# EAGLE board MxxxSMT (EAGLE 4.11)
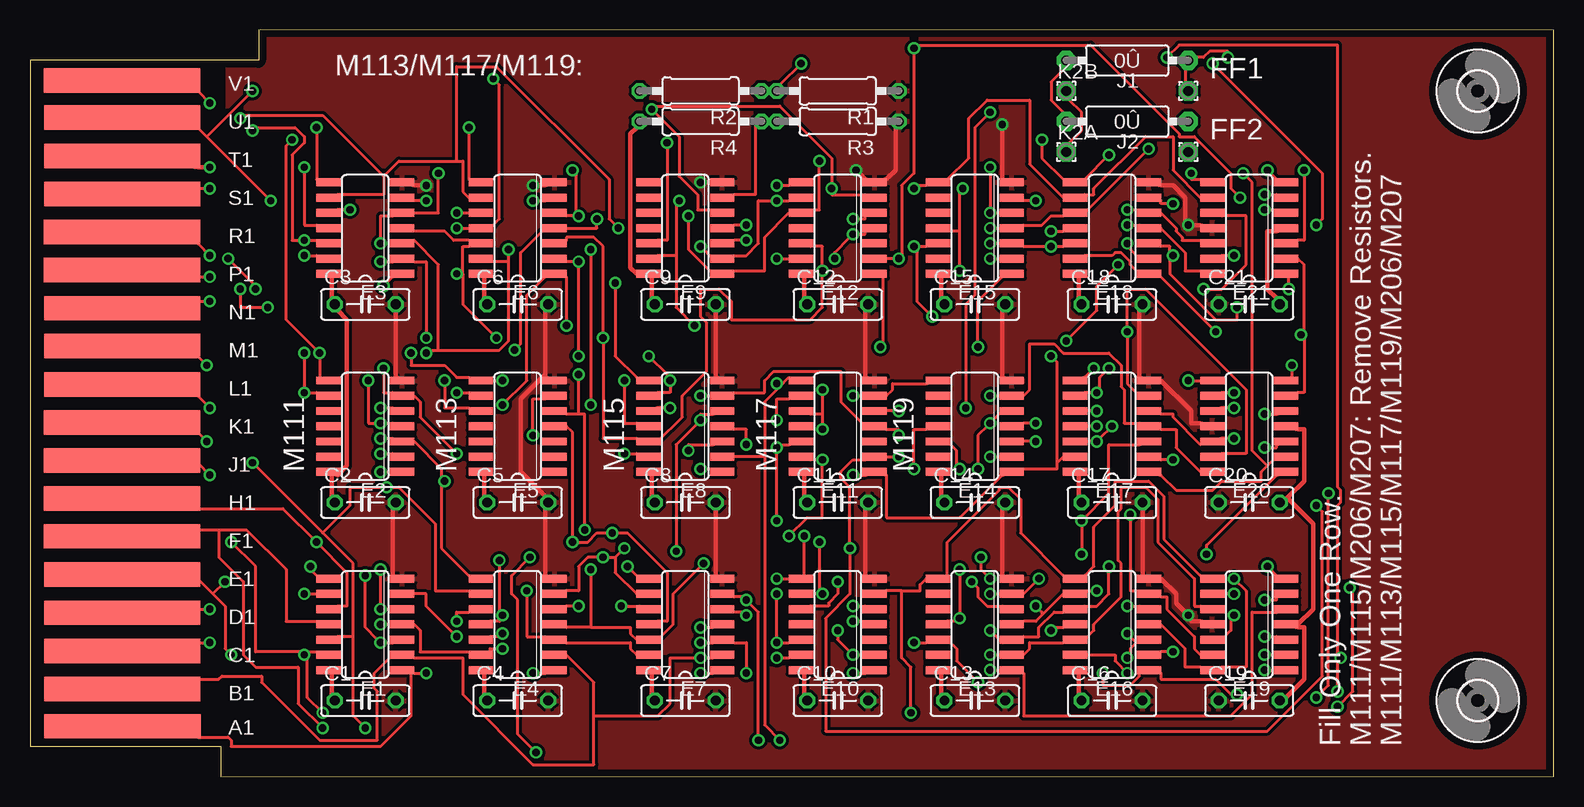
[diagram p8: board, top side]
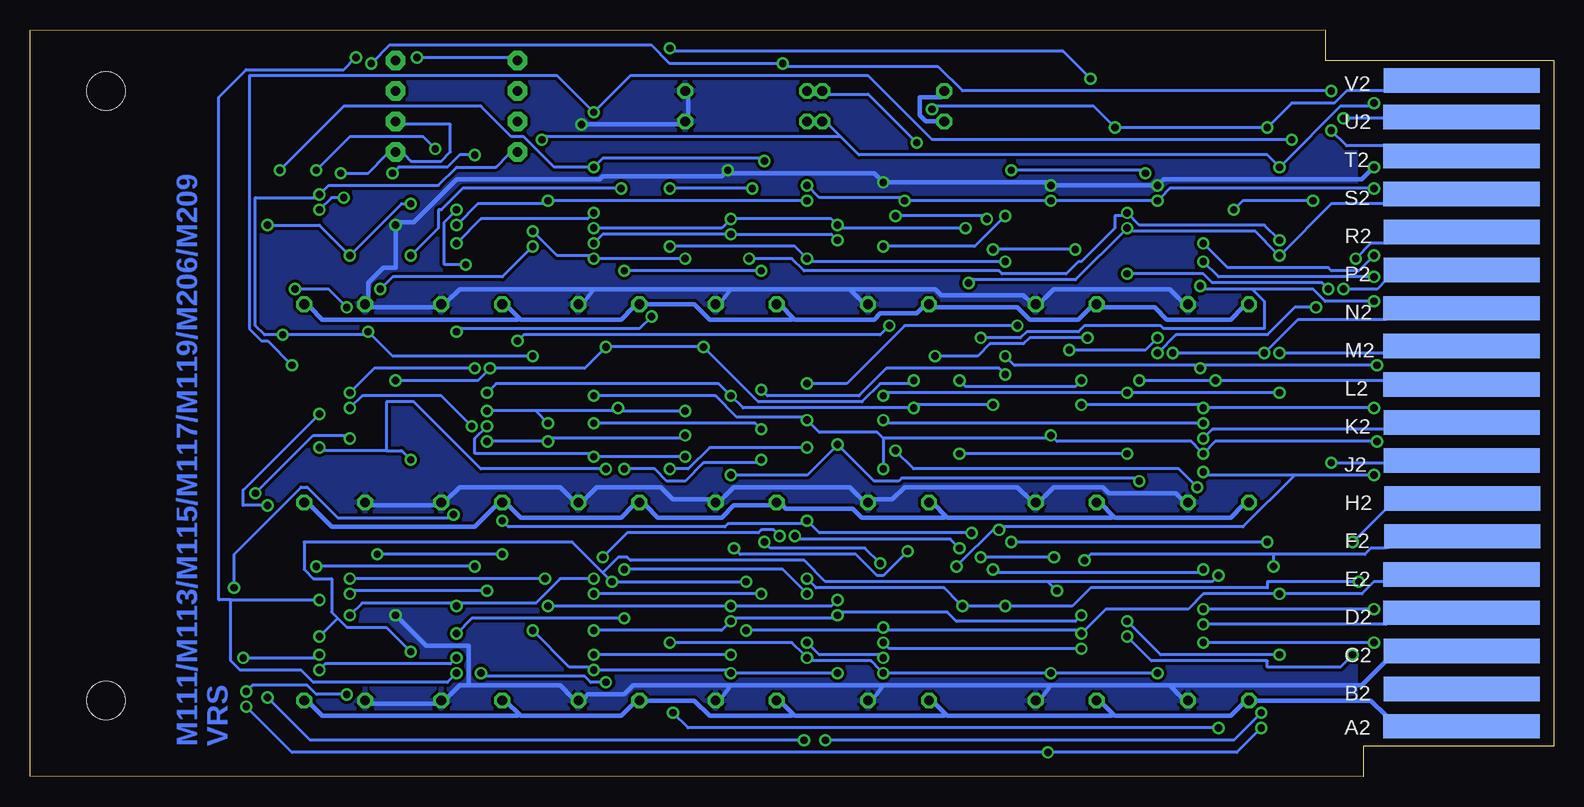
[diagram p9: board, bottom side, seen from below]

Size 126.99 x 62.23 mm. Coordinates in mm from the lower left corner, seen from the top.
Outline: 15.88,0 126.99,0.04 126.99,62.19 19.18,62.23
Copper layers (1*16): Top 0.035mm / dielectric 1.5mm / Bottom 0.035mm
Design rules "olimex10mil": minimum track width 10mil, minimum drill 24mil, track to track 10mil, track to pad 10mil, pad to pad 10mil, via to via 10mil, smd to smd 10mil, copper to edge 25mil, drill to drill 10mil, minimum pad ring 10mil, minimum via ring 8mil, stop-mask expansion 0mil, vias tented up to drill 0mil, thermal gap 10mil
Net classes: 1 Power: width 0.381 mm

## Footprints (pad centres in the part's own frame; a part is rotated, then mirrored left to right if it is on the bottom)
C050-025X075 = drill 0.813 octagon: 1 -2.54,0; 2 2.54,0
SO14 = smd 0.66 x 2.032: 1 -3.81,-3.073; 2 -2.54,-3.073; 3 -1.27,-3.073; 4 0,-3.073; 5 1.27,-3.073; 6 2.54,-3.073; 7 3.81,-3.073; 8 3.81,3.073; 9 2.54,3.073; 10 1.27,3.073; 11 0,3.073; 12 -1.27,3.073; 13 -2.54,3.073; 14 -3.81,3.073
1,6/0,8 = drill 0.813 pad 1.6 octagon: 1 0,0
0R/10 = drill 0.813 pad 1.6 octagon: 1 -5.08,0; 2 5.08,0
0207/10 = drill 0.813 octagon: 1 -5.08,0; 2 5.08,0
EDGE-CON2 = smd 13.017 x 2.032: A1 7.709,4.207; B1 7.684,7.312; C1 7.684,10.474; D1 7.684,13.665; E1 7.693,16.84; F1 7.668,20.041; H1 7.668,23.19; J1 7.668,26.34; K1 7.668,29.515; L1 7.693,32.69; M1 7.693,35.89; N1 7.693,39.04; P1 7.668,42.24; R1 7.668,45.39; S1 7.693,48.565; T1 7.693,51.74; U1 7.693,54.94; V1 7.668,58.026 | smd 13.017 x 2.032 bottom: A2 7.69,4.207; B2 7.668,7.328; C2 7.668,10.49; D2 7.693,13.665; E2 7.693,16.84; F2 7.642,20.041; H2 7.642,23.19; J2 7.668,26.34; K2 7.668,29.515; L2 7.693,32.69; M2 7.693,35.89; N2 7.693,39.04; P2 7.668,42.24; R2 7.668,45.39; S2 7.693,48.565; T2 7.693,51.74; U2 7.693,54.966; V2 7.668,58.026
3,2 = hole 3.2: 0,0

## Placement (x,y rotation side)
C1  0.1uf  [C050-025X075]  27.94,6.35 0 top
C2  0.1uf  [C050-025X075]  27.94,22.86 0 top
C3  0.1uf  [C050-025X075]  27.94,39.37 0 top
C4  0.1uf  [C050-025X075]  40.64,6.35 0 top
C5  0.1uf  [C050-025X075]  40.64,22.86 0 top
C6  0.1uf  [C050-025X075]  40.64,39.37 0 top
C7  0.1uf  [C050-025X075]  54.61,6.35 0 top
C8  0.1uf  [C050-025X075]  54.61,22.86 0 top
C9  0.1uf  [C050-025X075]  54.61,39.37 0 top
C10  0.1uf  [C050-025X075]  67.31,6.35 0 top
C11  0.1uf  [C050-025X075]  67.31,22.86 0 top
C12  0.1uf  [C050-025X075]  67.31,39.37 0 top
C13  0.1uf  [C050-025X075]  78.74,6.35 0 top
C14  0.1uf  [C050-025X075]  78.74,22.86 0 top
C15  0.1uf  [C050-025X075]  78.74,39.37 0 top
C16  0.1uf  [C050-025X075]  90.17,6.35 0 top
C17  0.1uf  [C050-025X075]  90.17,22.86 0 top
C18  0.1uf  [C050-025X075]  90.17,39.37 0 top
C19  0.1uf  [C050-025X075]  101.6,6.35 180 top
C20  0.1uf  [C050-025X075]  101.6,22.86 180 top
C21  0.1uf  [C050-025X075]  101.6,39.37 180 top
E1  7404D  [SO14]  27.94,12.7 90 top
E2  7404D  [SO14]  27.94,29.21 90 top
E3  7404D  [SO14]  27.94,45.72 90 top
E4  7400D  [SO14]  40.64,12.7 90 top
E5  7400D  [SO14]  40.64,29.21 90 top
E6  7400D  [SO14]  40.64,45.72 90 top
E7  7410D  [SO14]  54.61,12.7 90 top
E8  7410D  [SO14]  54.61,29.21 90 top
E9  7410D  [SO14]  54.61,45.72 90 top
E10  7420D  [SO14]  67.31,12.7 90 top
E11  7420D  [SO14]  67.31,29.21 90 top
E12  7420D  [SO14]  67.31,45.72 90 top
E13  7430D  [SO14]  78.74,12.7 90 top
E14  7430D  [SO14]  78.74,29.21 90 top
E15  7430D  [SO14]  78.74,45.72 90 top
E16  7474D  [SO14]  90.17,12.7 90 top
E17  7474D  [SO14]  90.17,29.21 90 top
E18  7474D  [SO14]  90.17,45.72 90 top
E19  7473D  [SO14]  101.6,12.7 90 top
E20  7473D  [SO14]  101.6,29.21 90 top
E21  7473D  [SO14]  101.6,45.72 90 top
FF1  [1,6/0,8]  96.52,57.15 0 top
FF2  [1,6/0,8]  96.52,52.07 0 top
J1  [0R/10]  91.44,59.69 0 top
J2  [0R/10]  91.44,54.61 0 top
K2A  [1,6/0,8]  86.36,52.07 0 top
K2B  [1,6/0,8]  86.36,57.15 0 top
R1  750  [0207/10]  67.31,57.15 180 top
R2  330  [0207/10]  55.88,57.15 180 top
R3  750  [0207/10]  67.31,54.61 180 top
R4  330  [0207/10]  55.88,54.61 180 top
U$1  [EDGE-CON2]  0,0 0 top
U$2  [3,2]  120.65,6.35 0 top
U$3  [3,2]  120.65,57.15 0 top

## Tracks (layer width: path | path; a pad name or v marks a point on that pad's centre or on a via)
A1  (via drill 0.61)
  Top 0.254: J2.1 86.11,55.37 85.09,56.39 85.09,57.91 86.11,58.93 J1.1 | U$1.A1 13.97,3.3 16.51,3.3 16.76,3.05 16.76,2.54 29.21,2.54 31.75,5.08 31.75,8.64 E1.1 32,8.64 v33.02,8.64 | v41.91,8.64 42.93,8.64 E4.1 | v55.88,8.64 56.9,8.64 E7.1 | v62.23,9.91 63.25,9.91 E10.13 | v73.66,11.18 74.68,11.18 E13.12 76.45,11.43 77.22,10.67 77.22,9.65 v78.99,7.87 | v89.41,8.64 89.41,7.62 91.69,7.62 92.46,8.38 92.46,8.64 E16.1 94.23,8.64 94.23,8.13 98.81,8.13 100.08,6.86 v100.58,6.86 | v102.87,10.16 103.89,10.16 E19.2 | v108.97,7.11 108.97,9.65 v109.22,9.91 108.97,10.16 108.97,22.61 109.22,22.86 109.22,23.88 108.97,24.13 108.97,60.96 95.76,60.96 v94.74,59.94
  Bottom 0.254: v33.02,8.64 v41.91,8.64 42.16,8.64 v55.88,8.64 56.13,8.89 56.9,9.65 61.98,9.65 v62.23,9.91 62.48,10.16 63.5,11.18 v73.66,11.18 | v89.41,8.64 89.15,8.38 80.77,8.38 80.26,7.87 v78.99,7.87 | v102.87,10.16 103.12,9.91 v109.22,9.91 | v108.97,7.11 108.46,7.62 103.89,7.62 103.12,6.86 v100.58,6.86 | v94.74,59.94 87.12,59.94 J1.1
B1  (via drill 0.61)
  Top 0.254: v102.87,8.89 103.89,8.89 E19.1 | v91.44,9.91 91.69,10.16 91.69,10.67 92.2,11.18 | 92.2,11.18 92.46,11.43 E16.3 | v91.44,11.94 92.2,11.18 | E13.11 76.45,12.95 77.47,12.95 v77.47,13.21 77.47,13.46 v77.47,17.27 | 46.99,5.08 46.99,7.87 44.7,10.16 E4.2 | 46.99,5.08 46.99,1.02 41.91,1.02 36.07,6.86 36.07,9.91 32,9.91 E1.2 30.23,10.16 28.7,8.64 28.7,7.37 28.96,7.11 28.96,3.05 24.13,3.05 19.3,7.87 19.3,8.38 16,8.38 15.75,8.13 13.97,8.13 U$1.B1 | 46.99,5.08 52.32,5.08 53.34,6.1 53.34,9.91 v55.88,9.91 56.9,9.91 E7.2 | E10.12 63.25,11.18 v62.23,11.18 62.23,11.43 v62.23,15.24
  Bottom 0.254: v102.87,8.89 102.36,9.4 91.95,9.4 v91.44,9.91 | v77.47,13.21 90.17,13.21 v91.44,11.94 | v62.23,11.18 61.21,10.16 56.13,10.16 v55.88,9.91 | v77.47,17.27 64.26,17.27 v62.23,15.24
C1  (via drill 0.61)
  Top 0.254: v14.99,11.18 13.97,11.18 U$1.C1 | E1.3 30.23,11.18 v29.21,11.18 28.96,11.43 27.94,12.45 v27.94,16.76 | E7.13 50.55,10.16 50.04,10.67 50.04,11.18 44.7,11.18 E4.3 42.93,11.68 41.4,11.68 v41.4,15.49 | v67.31,16.26 67.31,15.24 66.55,14.48 66.55,14.22 65.02,14.22 E10.10 | v78.49,16.26 78.99,15.75 78.99,14.99 79.76,14.22 81.03,14.22 E13.5 | v95.25,10.41 94.23,10.41 E16.2 | v102.87,11.68 103.89,11.68 E19.3
  Bottom 0.254: v14.99,11.18 v29.21,11.18 | v67.31,16.26 v78.49,16.26 78.74,16.51 79.25,17.02 | v95.25,10.41 97.28,12.45 100.58,12.45 101.35,13.21 | 101.35,13.21 101.85,13.72 101.85,16.51 103.38,16.51 104.14,17.27 104.14,19.56 81.79,19.56 79.25,17.02 | 101.35,13.21 v102.87,11.68 | 42.16,16.26 v41.4,15.49 | 42.16,16.26 60.71,16.26 62.48,18.03 76.96,18.03 77.22,18.29 77.98,18.29 79.25,17.02 | v27.94,16.76 28.45,16.26 42.16,16.26
D1  (via drill 0.61)
  Top 0.254: E16.4 94.23,12.7 96.27,10.67 96.27,9.14 97.54,9.14 E19.14 99.31,9.14 101.35,9.14 101.35,15.49 v100.33,16.51 | v80.01,15.24 81.03,15.24 E13.6 82.8,15.24 v84.07,16.51 | E10.9 65.02,15.24 v66.04,15.24 65.79,15.49 v65.79,19.56 | 46.74,12.45 50.04,12.45 50.04,11.94 50.55,11.43 E7.12 52.32,11.43 53.59,12.7 53.59,15.24 v56.13,17.78 | 46.74,12.45 44.7,12.45 E4.4 | v14.99,13.97 13.97,13.97 U$1.D1 | E1.5 30.23,13.97 v29.21,13.97 29.21,14.22 v29.21,17.27 | v46.74,17.27 46.74,12.45
  Bottom 0.254: v66.04,15.24 v80.01,15.24 | v84.07,16.51 v100.33,16.51 | v14.99,13.97 v29.21,13.97 | v46.74,17.27 46.48,17.02 29.46,17.02 v29.21,17.27 | v65.79,19.56 65.28,19.05 57.4,19.05 v56.13,17.78
D2  (via drill 0.61)
  Top 0.254: v59.69,8.64 59.69,11.18 58.67,11.18 E7.3 56.9,11.18 v55.88,11.18 | v68.58,8.64 69.6,8.64 E10.1 | v80.01,8.89 81.03,8.89 E13.1 82.8,8.64 82.8,5.08 100.08,5.08 101.85,6.86 101.85,13.72 103.89,13.72 E19.5 | v85.09,12.19 85.09,12.45 86.11,12.45 E16.11 | v29.21,12.7 30.23,12.7 E1.4 32,12.7 32.51,12.19 32.51,10.41 36.58,10.41 E4.13 38.35,10.41 38.35,10.67 v39.37,10.67
  Bottom 0.254: v59.69,8.64 v68.58,8.64 68.83,8.89 v80.01,8.89 80.26,9.14 82.04,9.14 v85.09,12.19 | v29.21,12.7 13.97,12.7 U$1.D2 | v55.88,11.18 55.37,10.67 v39.37,10.67
E1  (via drill 0.61)
  Top 0.254: v91.44,14.22 92.46,14.22 E16.5 | v100.33,13.46 100.08,13.21 100.08,12.19 99.31,11.43 E19.12 | v80.01,16.51 79.25,17.27 v79.25,18.29 | v64.52,20.07 64.52,16.76 E10.8 63.25,16.51 v62.23,16.51 | v45.72,14.22 44.7,14.22 E4.5 | v49.28,14.22 50.8,14.22 E7.10 | v35.56,11.68 33.02,14.22 33.02,15.24 32,15.24 E1.6 | v16.76,10.16 16.26,10.67 16.26,14.22 15.24,15.24 | 15.24,15.24 13.72,16.76 U$1.E1 | 15.24,15.24 v16.26,16.26
  Bottom 0.254: v100.33,13.46 99.31,14.48 91.69,14.48 v91.44,14.22 91.19,14.48 84.84,14.48 82.8,16.51 v80.01,16.51 | v79.25,18.29 77.22,20.32 66.29,20.32 66.04,20.57 65.02,20.57 v64.52,20.07 | v35.56,11.68 33.53,9.65 23.88,9.65 23.88,9.14 17.78,9.14 v16.76,10.16 | v16.26,16.26 23.88,16.26 23.88,15.75 38.61,15.75 40.13,14.22 v45.72,14.22 v49.28,14.22 49.53,14.48 50.8,15.75 61.47,15.75 v62.23,16.51
E2  (via drill 0.61)
  Top 0.254: v80.01,10.16 81.03,10.16 E13.2 82.8,10.16 83.31,10.67 83.31,11.18 86.11,11.18 E16.12 87.88,11.43 88.65,12.19 88.65,12.7 90.93,14.99 90.93,17.78 90.68,18.03 90.68,22.1 90.93,22.35 90.93,24.13 92.96,24.13 93.98,23.11 93.98,19.56 97.03,16.51 97.03,14.22 97.54,14.22 E19.10 | E10.2 69.6,10.16 v68.58,10.16 68.33,10.41 67.31,11.43 v67.31,12.19 | v39.37,11.94 39.37,11.68 38.35,11.68 E4.12 | v55.88,12.45 56.9,12.45 E7.4 | v22.86,15.24 23.88,15.24 E1.9
  Bottom 0.254: v68.58,10.16 v80.01,10.16 | U$1.E2 13.97,16.26 14.99,16.26 16,15.24 v22.86,15.24 29.21,15.24 30.48,13.97 37.34,13.97 v39.37,11.94 39.62,12.19 55.63,12.19 v55.88,12.45 56.13,12.19 v67.31,12.19
F1  (via drill 0.61)
  Top 0.254: 15.75,20.57 13.97,20.57 U$1.F1 | 15.75,20.57 18.03,20.57 21.34,17.27 21.34,12.95 23.88,12.95 E1.11 | E19.13 97.54,10.16 97.03,10.67 97.03,11.68 94.74,13.97 94.74,14.99 94.23,14.99 E16.6 92.46,15.49 91.69,15.49 v91.69,21.84 | 48.77,18.29 v47.75,18.29 46.48,18.29 45.72,17.53 45.72,15.49 44.7,15.49 E4.6 | 48.77,18.29 48.77,17.02 50.55,15.24 E7.9 | v77.47,25.65 77.22,25.91 77.22,27.18 76.45,27.94 E14.12 | E11.13 65.02,26.42 v66.04,26.42 66.04,26.16 66.04,21.59 64.77,21.59 v63.25,20.07 | 48.77,18.29 v49.53,19.05 | v24.38,4.06 22.35,6.1 22.35,9.14 18.8,9.14 17.78,10.16 17.78,16.26 15.75,18.29 15.75,20.32 15.75,20.57 | v42.16,2.03 40.64,3.56 40.64,14.73 40.13,15.24 40.13,16.76 v41.66,18.29 | v109.98,15.75 110.24,15.49 110.24,7.11 v108.97,5.84
  Bottom 0.254: v66.04,26.42 66.29,26.16 70.87,26.16 72.39,24.64 73.91,24.64 74.93,25.65 v77.47,25.65 | v49.53,19.05 50.29,19.81 62.99,19.81 v63.25,20.07 | v24.38,4.06 26.42,2.03 v42.16,2.03 42.42,2.03 105.16,2.03 v108.97,5.84 | v41.66,18.29 v47.75,18.29 | v91.69,21.84 91.95,21.59 101.35,21.59 103.89,24.13 104.39,24.13 109.98,18.54 v109.98,15.75
F2  (via drill 0.61)
  Top 0.254: v59.69,13.46 59.69,13.72 58.67,13.72 E7.5 | v68.58,12.95 69.6,12.95 E10.4 | v103.12,17.53 103.89,16.76 E19.7 | v89.92,17.53 89.92,15.24 88.9,14.22 87.88,14.22 E16.10 86.11,13.72 85.34,13.72 84.07,12.45 84.07,11.68 82.8,11.68 E13.3 81.03,11.18 v80.01,12.19 | v39.12,18.03 39.12,13.46 | 39.12,13.46 39.12,12.95 38.35,12.95 E4.11 | v23.37,17.53 23.37,17.27 23.88,16.76 E1.8 | 39.12,13.46 v39.37,13.46
  Bottom 0.254: v89.92,17.53 v103.12,17.53 | v80.01,12.19 69.34,12.19 68.83,12.7 v68.58,12.95 68.33,13.21 59.94,13.21 v59.69,13.46 59.44,13.72 50.55,13.72 49.78,12.95 39.88,12.95 v39.37,13.46 | v39.12,18.03 38.61,18.54 23.37,18.54 | 23.37,18.54 15.75,18.54 15.24,19.05 13.97,19.05 U$1.F2 | 23.37,18.54 v23.37,17.53
FF1  (via drill 0.61)
  Top 0.254: FF1.1 96.27,57.91 96.27,58.93 J1.2 97.28,59.94 97.79,59.94 98.3,60.45 99.82,60.45 v99.82,59.94 | v91.44,8.64 90.42,9.65 90.42,10.16 87.88,10.16 E16.13 | v102.87,14.73 103.89,14.73 103.89,14.99 E19.6
  Bottom 0.254: v91.44,8.64 92.2,7.87 103.38,7.87 104.39,8.89 109.47,8.89 110.24,9.65 110.24,14.73 | 110.24,14.73 v102.87,14.73 | v99.82,59.94 100.84,58.93 108.97,58.93 111.25,56.64 111.25,14.73 110.24,14.73
FF2  (via drill 0.61)
  Top 0.254: 103.12,25.91 103.89,26.67 E20.2 | 103.12,25.91 102.62,25.4 102.62,24.64 99.31,24.64 98.55,23.88 95.5,23.88 94.23,25.15 E17.1 | v101.09,50.29 101.85,49.53 101.85,27.18 103.12,25.91
  Bottom 0.254: J2.2 95.76,54.36 91.95,54.36 91.95,52.07 92.71,51.31 95.25,51.31 95.76,51.82 FF2.1 97.28,51.82 98.81,50.29 v101.09,50.29
GND  (via drill 0.61)
  Top 0.381: R3.1 72.14,54.1 72.14,50.55 71.37,49.78 E12.7 69.6,49.78 v68.83,50.55 | v81.03,54.36 81.03,49.78 E15.7 | v33.02,49.28 32,49.28 E3.7 | v41.91,49.28 42.93,49.28 E6.7 | v55.88,49.53 56.9,49.53 E9.7 | v14.99,50.8 13.97,50.8 U$1.T1 | E13.7 81.03,16.76 81.03,22.35 C14.2 | C17.2 92.71,22.35 92.71,16.76 E16.7 94.23,16.51 95.5,15.24 95.5,14.48 v96.52,13.46 96.77,13.46 96.77,12.95 97.54,12.95 E19.11 | E1.7 30.23,16.76 30.23,22.35 C2.2 | E4.7 42.93,16.76 42.93,22.35 C5.2 42.93,23.37 40.89,25.4 40.89,31.5 42.93,33.53 | E7.7 57.15,16.76 57.15,22.35 C8.2 | E10.7 69.6,16.76 69.6,22.35 C11.2 | E2.7 30.48,33.27 30.48,38.86 C3.2 | 42.93,33.53 42.93,38.86 C6.2 | 42.93,33.53 42.93,33.27 E5.7 | E21.11 97.54,45.97 v96.52,45.97 96.27,45.97 96.27,48.26 95.25,49.28 94.23,49.28 E18.7 | E20.11 97.54,29.46 96.77,29.46 96.77,30.48 94.23,33.02 E17.7 92.46,33.27 92.46,38.86 C18.2 | E14.7 81.03,33.27 81.03,38.86 C15.2 | E8.7 57.15,33.27 57.15,38.86 C9.2 | E11.7 69.6,33.27 69.6,38.86 C12.2
  Bottom 0.381: 90.42,7.62 91.19,7.62 92.2,6.6 C16.2 93.22,6.1 98.55,6.1 C19.2 | 90.42,7.62 82.8,7.62 81.79,6.6 C13.2 80.77,6.6 80.52,6.86 77.47,6.86 76.71,7.62 68.58,7.62 | 32,7.62 30.99,6.6 C1.2 | 32,7.62 41.66,7.62 41.91,7.62 | 41.91,7.62 42.67,6.6 C4.2 | 55.88,7.62 55.63,7.62 41.91,7.62 | 55.88,7.62 56.64,6.6 C7.2 | 68.58,7.62 68.33,7.62 55.88,7.62 | 68.58,7.62 69.34,6.6 C10.2 | U$1.C2 13.97,9.65 16,7.62 31.75,7.62 32,7.62 | v81.03,54.36 72.9,54.36 R3.1 72.14,55.12 72.14,56.64 R1.1 | v14.99,50.8 16,49.78 32.51,49.78 32.77,49.53 v33.02,49.28 v41.91,49.28 42.16,49.53 v55.88,49.53 56.13,49.78 56.64,50.29 68.58,50.29 v68.83,50.55 69.09,50.29 69.34,50.04 79.25,50.04 79.5,49.78 91.44,49.78 95,46.23 96.27,46.23 v96.52,45.97 96.52,42.42 97.54,42.42 98.81,41.15 98.81,39.88 C21.2 98.55,39.12 93.22,39.12 C18.2 92.2,39.62 91.19,40.64 80.01,40.64 | C20.2 98.55,22.61 93.22,22.61 C17.2 92.2,23.11 91.19,24.13 82.8,24.13 81.79,23.11 C14.2 80.77,23.11 79.76,24.13 74.42,24.13 73.41,23.11 70.36,23.11 C11.2 69.34,23.11 68.33,24.13 58.67,24.13 57.66,23.11 C8.2 56.64,23.11 55.12,23.11 54.1,24.13 44.7,24.13 43.69,23.11 C5.2 42.67,23.11 41.66,24.13 37.59,24.13 37.08,23.62 31.5,23.62 30.99,23.11 C2.2 | C3.2 30.99,39.62 32,40.64 41.66,40.64 42.67,39.62 C6.2 43.69,39.62 44.2,40.13 51.05,40.13 51.56,40.64 58.42,40.64 58.67,40.64 | 58.67,40.64 57.66,39.62 C9.2 | 58.67,40.64 68.33,40.64 68.58,40.64 | 68.58,40.64 69.34,39.62 C12.2 | 80.01,40.64 79.76,40.64 68.58,40.64 | 80.01,40.64 80.77,39.62 C15.2 | 90.42,7.62 90.42,10.92 93.98,10.92 v96.52,13.46
  pour Bottom: 16.51,0 16.51,62.23 127,62.23 127,0
  pour Top: 16.51,0 16.51,62.23 127,62.23 127,0
H1  (via drill 0.61)
  Top 0.254: E1.10 25.65,14.22 26.42,14.22 26.42,17.02 v23.88,19.56 21.08,22.35 13.97,22.35 U$1.H1 | E7.11 52.32,12.95 53.09,12.95 53.09,17.02 49.78,20.32 v48.51,20.32 47.24,20.32 46.48,19.56 v45.21,19.56 45.21,28.7 44.7,29.21 E5.4 | v62.23,21.34 v62.23,27.43 62.23,27.69 63.25,27.69 E11.12 | E17.3 92.46,27.69 89.92,27.69 89.92,23.62 v87.63,21.34 87.63,21.08 v87.63,18.54 | v98.04,18.54 98.04,19.3 103.89,25.15 E20.1 | v73.66,25.65 73.66,28.96 74.68,28.96 E14.11
  Bottom 0.254: v48.51,20.32 61.21,20.32 v62.23,21.34 62.48,21.08 68.83,21.08 69.09,20.83 87.12,20.83 v87.63,21.34 | v87.63,18.54 v98.04,18.54 | v73.66,25.65 72.14,25.65 70.36,27.43 v62.23,27.43 | v23.88,19.56 v45.21,19.56
H2  (via drill 0.61)
  Top 0.254: v68.58,14.22 69.6,14.22 E10.5 | E7.6 58.67,14.99 59.69,14.99 v59.69,14.73 59.94,14.48 60.71,13.72 v60.71,3.05 | 84.33,13.46 86.11,15.24 E16.9 87.88,15.49 v88.9,15.49 | 84.33,13.46 83.82,12.95 82.8,12.95 E13.4 | v100.33,15.24 99.31,15.24 E19.9 | v83.82,14.22 84.33,13.72 84.33,13.46 | 22.86,10.41 18.8,10.41 18.8,17.53 v16.76,19.56 | 22.86,10.41 23.88,10.41 E1.13 | v35.56,12.95 35.56,13.72 36.58,13.72 E4.10 | 22.86,10.41 v22.86,10.16 23.11,9.91 23.11,6.6 v24.38,5.33
  Bottom 0.254: v59.69,14.73 60.2,14.22 v68.58,14.22 68.83,14.22 v83.82,14.22 | v100.33,15.24 100.08,15.49 v88.9,15.49 | v16.76,19.56 13.97,22.35 U$1.H2 | v35.56,12.95 32.77,10.16 v22.86,10.16 | v60.71,3.05 26.67,3.05 v24.38,5.33
J1  (via drill 0.61)
  Top 0.254: v95.25,26.42 94.23,26.42 E17.2 | v102.87,27.43 103.89,27.43 103.89,27.69 E20.3 | 66.04,30.23 65.02,30.23 E11.10 | 66.04,30.23 v66.04,28.96 | E14.5 81.03,30.48 v80.01,29.46 79.76,29.21 78.99,28.45 v78.99,25.65 | v29.21,25.4 30.23,25.4 E2.1 | v14.99,25.15 13.97,26.16 U$1.J1 | v49.78,17.53 50.55,16.76 E7.8 | 45.72,30.23 46.23,30.23 v46.23,20.57 | 45.72,30.23 44.7,30.23 E5.5 | v66.04,32.26 66.04,30.23 | 45.72,30.23 v45.72,33.53
  Bottom 0.254: v95.25,26.42 96.01,27.18 97.28,27.18 | 97.28,27.18 102.62,27.18 v102.87,27.43 | v66.04,28.96 66.55,29.46 v80.01,29.46 | 97.28,27.18 97.28,31.24 95,31.24 89.41,25.65 v78.99,25.65 | v29.21,25.4 28.96,25.15 21.59,25.15 | v14.99,25.15 21.59,25.15 | v49.78,17.53 46.48,20.83 46.23,20.83 | 46.23,20.83 25.91,20.83 21.59,25.15 | 46.23,20.83 v46.23,20.57 | v66.04,32.26 65.53,31.75 57.91,31.75 55.63,34.04 46.23,34.04 v45.72,33.53
J2  (via drill 0.61)
  Top 0.254: 72.64,15.49 74.17,15.49 74.17,16 74.68,16.51 E13.8 76.45,16.76 76.45,19.56 80.77,23.88 80.77,24.13 81.53,24.13 82.55,23.11 82.55,20.32 86.11,16.76 E16.8 87.88,16.76 88.65,17.53 88.65,20.83 90.42,22.61 90.42,24.64 93.22,24.64 94.49,23.37 94.49,19.81 97.54,16.76 E19.8 | 72.64,15.49 71.37,15.49 E10.6 | 26.92,11.68 25.65,11.68 E1.12 | 26.92,11.68 26.92,17.78 24.38,20.32 | 24.38,20.32 v18.54,26.16 | 24.38,20.32 26.67,22.61 26.67,24.13 v29.72,24.13 30.73,24.13 33.78,21.08 33.78,15.49 36.58,15.49 E4.9 | v54.86,27.18 54.86,27.69 56.9,27.69 E8.3 | 72.64,15.49 72.64,9.91 73.41,9.14 v73.41,5.33 | v27.94,4.06 26.92,5.08 26.92,11.68
  Bottom 0.254: v18.54,26.16 13.97,26.16 U$1.J2 | v54.86,27.18 53.34,25.65 31.24,25.65 v29.72,24.13 | v73.41,5.33 72.14,4.06 v27.94,4.06
K1  (via drill 0.61)
  Top 0.254: E20.14 97.54,25.4 95.5,27.43 95.5,28.96 94.23,28.96 E17.4 92.46,29.46 91.19,29.46 91.19,32.26 90.93,32.51 90.93,34.29 89.92,35.31 86.11,35.31 85.34,36.07 83.31,36.07 83.31,32.26 82.8,31.75 E14.6 81.03,31.75 v80.01,31.75 | v29.21,26.92 30.23,26.92 E2.2 | v14.73,27.94 13.97,28.7 U$1.K1 | v41.91,28.45 41.91,31.5 42.93,31.5 E5.6 | v55.88,25.65 56.9,25.65 E8.1 | v62.23,29.72 62.23,31.5 63.25,31.5 E11.9
  Bottom 0.254: v14.73,27.94 28.19,27.94 v29.21,26.92 29.46,27.18 30.23,27.94 41.4,27.94 v41.91,28.45 42.16,28.19 55.88,28.19 | 55.88,28.19 v55.88,25.65 | 55.88,28.19 56.39,28.7 61.21,28.7 v62.23,29.72 62.48,29.97 68.07,29.97 69.85,31.75 v80.01,31.75
K2  (via drill 0.61)
  Top 0.254: 106.17,36.83 106.17,42.67 105.66,43.18 E21.2 | 106.17,36.83 106.17,32 105.66,32 E20.6 | E18.13 87.88,43.43 90.17,43.43 90.42,43.69 90.93,43.69 91.69,42.93 91.69,42.67 92.46,41.91 E18.1 94.23,41.66 v98.81,37.08 | v102.87,48.51 103.89,48.51 E21.6 | K2B.1 86.61,56.39 87.63,55.37 87.63,53.85 86.61,52.83 K2A.1 | v105.92,36.83 106.17,36.83 | 85.6,26.16 85.6,25.65 82.8,25.65 E14.1 81.03,25.15 77.47,21.59 71.37,21.59 71.37,25.15 E11.1 69.6,25.15 v68.58,25.15 | 85.6,26.16 86.11,26.67 E17.13 | v59.69,27.69 59.69,28.96 58.67,28.96 E8.4 | 34.29,24.64 34.29,25.65 32,27.94 E2.3 30.23,28.19 v29.21,28.19 | 34.29,24.64 34.29,19.05 36.58,16.76 E4.8 | 34.29,24.64 v34.54,24.64 | v85.09,35.05 85.6,34.54 85.6,26.16
  Bottom 0.254: K2A.1 87.12,51.82 88.14,50.8 91.44,50.8 92.96,49.28 102.11,49.28 v102.87,48.51 103.12,48.26 108.2,48.26 108.2,37.59 107.44,36.83 v105.92,36.83 99.06,36.83 v98.81,37.08 98.55,36.83 96.77,35.05 v85.09,35.05 | v68.58,25.15 62.23,25.15 v59.69,27.69 59.44,27.43 56.64,24.64 54.61,24.64 54.36,24.89 34.8,24.89 v34.54,24.64 | v29.21,28.19 28.45,28.96 13.97,28.96 U$1.K2
L1  (via drill 0.61)
  Top 0.254: v29.21,30.73 30.23,30.73 E2.5 | v14.99,30.73 13.97,31.75 U$1.L1 | v39.37,30.99 41.4,33.02 41.4,40.13 42.93,41.66 E6.1 44.7,41.66 v44.7,37.59 | E17.5 94.23,30.23 95.25,30.23 95.25,29.97 97.54,27.69 E20.12 99.31,28.19 v100.33,28.19 | 61.21,26.67 58.67,26.67 E8.2 | 61.21,26.67 61.21,31.24 62.48,32.51 | 62.48,32.51 63.25,33.27 E11.8 | v108.2,23.62 108.2,7.62 v107.19,6.6 | v62.48,3.05 61.21,4.32 61.21,26.67 | v62.23,32.77 62.48,32.51
  Bottom 0.254: v14.99,30.73 v29.21,30.73 29.46,30.99 v39.37,30.99 | v100.33,28.19 100.58,28.45 103.38,28.45 v108.2,23.62 | v107.19,6.6 103.63,3.05 v62.48,3.05 | v44.7,37.59 54.1,37.59 58.93,32.77 v62.23,32.77
L2  (via drill 0.61)
  Top 0.254: v72.39,26.67 71.37,26.67 E11.2 69.6,26.42 68.58,26.42 67.56,25.4 67.56,24.89 68.33,24.13 v68.33,19.05 68.33,15.24 66.29,13.21 66.29,3.81 103.12,3.81 107.7,8.38 107.7,22.1 v107.19,22.61 | v80.01,26.67 81.03,26.67 E14.2 | v88.9,29.21 87.88,29.21 E17.11 | v102.87,30.23 103.89,30.23 E20.5 | v28.19,33.02 28.19,29.46 v29.21,29.46 30.23,29.46 E2.4 | v34.54,33.02 34.54,30.73 36.58,30.73 E5.10 | E8.5 56.9,30.23 55.88,30.23 v55.88,29.72 55.63,29.46 53.85,27.69 v53.85,18.8
  Bottom 0.254: v72.39,26.67 v80.01,26.67 80.26,26.92 89.92,26.92 89.92,28.19 v88.9,29.21 | v102.87,30.23 109.22,23.88 109.22,22.61 v107.19,22.61 | U$1.L2 13.97,33.02 v28.19,33.02 28.45,33.02 v34.54,33.02 | v55.88,29.72 55.63,29.46 v29.21,29.46 | v68.33,19.05 67.82,18.54 58.17,18.54 56.39,16.76 55.88,16.76 v53.85,18.8
M1  (via drill 0.61)
  Top 0.254: E20.13 99.31,26.92 101.35,26.92 101.35,32.26 92.96,40.64 91.44,40.64 v91.44,37.08 91.44,32.77 92.46,31.75 E17.6 | v29.46,34.04 29.46,32 30.23,32 E2.6 32,31.75 32.51,31.24 32.51,29.97 v35.56,26.92 | v14.73,34.29 13.97,35.05 U$1.M1 | v45.72,35.05 v45.72,42.93 44.7,42.93 E6.2 | v49.53,26.92 50.55,26.92 E8.13 | v62.23,43.18 63.25,43.18 E12.13 | E15.12 74.68,44.2 v73.66,44.2 73.91,43.94 73.91,39.62 v75.18,38.35
  Bottom 0.254: v14.73,34.29 29.21,34.29 v29.46,34.04 29.72,34.29 44.96,34.29 v45.72,35.05 | v35.56,26.92 v49.53,26.92 | v45.72,42.93 61.98,42.93 v62.23,43.18 62.48,43.43 63.25,44.2 v73.66,44.2 | v91.44,37.08 91.19,37.34 76.2,37.34 v75.18,38.35
M2  (via drill 0.61)
  Top 0.254: v83.82,27.94 82.8,27.94 E14.3 | E17.12 87.88,27.94 v88.9,27.94 89.15,28.19 v90.17,29.21 | v72.39,28.45 72.39,28.96 71.37,28.96 E11.4 69.6,29.21 67.56,31.24 67.56,33.78 61.98,33.78 61.21,33.02 61.21,32 58.67,32 E8.6 56.9,31.75 v55.88,31.75 | v100.33,30.73 99.31,30.73 E20.10 | v22.86,35.31 v22.86,32 23.88,32 E2.9 | v35.56,32 36.58,32 E5.9
  Bottom 0.254: v88.9,27.94 v83.82,27.94 83.57,28.19 72.64,28.19 v72.39,28.45 | v100.33,30.73 99.31,31.75 92.71,31.75 v90.17,29.21 | v22.86,35.31 13.97,35.31 U$1.M2 | v22.86,32 v35.56,32 35.81,32 55.63,32 v55.88,31.75
N1  (via drill 0.61)
  Top 0.254: 95,43.43 95,41.91 98.81,38.1 100.58,38.1 v100.58,39.12 | 95,43.43 95,44.2 94.23,44.2 E18.3 | v104.9,40.64 104.9,41.66 E21.1 | E6.3 44.7,44.7 44.7,44.96 46.99,44.96 47.75,44.2 v47.75,36.58 47.75,28.19 50.55,28.19 E8.12 52.32,27.94 54.36,29.97 54.36,31.75 56.39,33.78 56.39,37.85 55.88,38.35 55.88,40.64 57.4,40.64 58.42,39.62 58.42,38.1 65.02,38.1 66.04,39.12 v66.04,42.16 66.04,44.2 65.02,44.2 E12.12 | v29.46,40.89 30.23,41.66 E3.1 | 77.47,45.47 76.45,45.47 E15.11 | v77.47,42.16 77.47,45.47 | v95.25,43.43 95,43.43 | v77.72,49.02 77.47,48.77 77.47,45.47 | v14.99,39.62 13.97,39.62 U$1.N1
  Bottom 0.254: v100.58,39.12 102.11,40.64 v104.9,40.64 | v29.46,40.89 29.21,40.64 25.15,40.64 | 25.15,40.64 24.13,39.62 24.13,37.34 32.51,37.34 32.77,37.59 39.12,37.59 39.62,37.08 43.94,37.08 44.45,36.58 v47.75,36.58 | v66.04,42.16 v77.47,42.16 | v95.25,43.43 92.96,45.72 92.96,47.24 92.71,47.24 90.93,49.02 v77.72,49.02 | v14.99,39.62 19.05,39.62 20.07,40.64 25.15,40.64
N2  (via drill 0.61)
  Top 0.254: v83.82,29.46 82.8,29.46 E14.4 | v88.9,30.48 87.88,30.48 E17.10 | v72.39,30.48 71.37,30.48 E11.5 | v105.16,34.29 105.16,33.27 E20.7 | v80.01,55.37 78.74,54.1 78.74,40.13 77.98,39.37 v77.98,30.73 | E2.8 24.13,33.27 v24.13,35.31 23.88,35.56 21.34,38.1 21.34,52.58 v21.84,53.09 | v31.75,35.31 31.75,34.29 34.54,34.29 35.56,33.27 36.58,33.27 E5.8 38.35,33.02 v39.37,33.02 | v49.53,33.02 49.53,29.46 50.55,29.46 E8.11
  Bottom 0.254: 84.84,30.48 v83.82,29.46 | 84.84,30.48 v88.9,30.48 | 77.98,30.48 84.84,30.48 | 77.98,30.48 v72.39,30.48 | v105.16,34.29 107.19,36.32 107.7,36.32 108.71,37.34 108.71,58.42 83.06,58.42 v80.01,55.37 79.76,55.63 76.96,58.42 57.15,58.42 51.82,53.09 v21.84,53.09 | v77.98,30.73 77.98,30.48 | U$1.N2 13.97,38.1 21.34,38.1 v24.13,35.31 24.38,35.31 v31.75,35.31 | v49.53,33.02 49.02,32.51 39.88,32.51 v39.37,33.02
P1  (via drill 0.61)
  Top 0.254: v29.21,42.93 30.23,42.93 E3.2 32,42.93 33.02,42.93 v33.02,36.58 | v14.99,41.66 13.97,41.66 U$1.P1 | v47.24,46.48 47.24,45.72 44.7,45.72 E6.4 42.93,45.72 40.89,43.69 40.89,36.07 v40.39,35.56 | v54.86,46.74 54.86,43.94 56.9,41.91 E9.1 58.67,42.16 61.21,42.16 61.21,44.96 63.25,46.99 E12.10 65.02,47.24 65.79,47.24 v65.79,51.31 | v91.44,44.45 91.69,44.2 91.69,43.94 92.46,43.18 E18.2 | E15.5 81.03,46.99 v80.01,46.99 80.01,47.24 v80.01,50.8 | v106.17,50.55 106.17,44.7 105.66,44.7 E21.3
  Bottom 0.254: v29.21,42.93 27.94,41.66 v14.99,41.66 | v47.24,46.48 47.5,46.74 v54.86,46.74 | v80.01,46.99 80.52,46.48 89.41,46.48 v91.44,44.45 | v106.17,50.55 100.84,55.88 89.41,55.88 86.87,53.34 85.85,53.34 83.31,50.8 v80.01,50.8 79.76,51.05 79.25,51.56 66.04,51.56 v65.79,51.31 | v33.02,36.58 34.04,35.56 v40.39,35.56
P2  (via drill 0.61)
  Top 0.254: v53.34,30.73 52.32,30.73 E8.10 | v68.58,31.75 69.6,31.75 E11.6 71.37,31.75 71.88,32.26 71.88,32.77 74.68,32.77 E14.8 | E17.9 87.88,32 v88.9,32 89.15,32.26 89.15,33.27 v89.92,34.04 | v100.33,32 99.31,32 E20.9 | 39.88,42.93 38.35,42.93 E6.13 | 39.88,42.93 39.88,36.32 39.12,35.56 34.04,35.56 | 34.04,35.56 34.04,42.67 32,44.7 E3.3 | 34.04,35.56 33.02,35.56 v33.02,35.31 | v19.81,39.12 17.53,39.12 v17.53,40.64 | v46.74,43.94 v46.74,30.99 | 39.88,42.93 v39.88,43.94
  Bottom 0.254: v88.9,32 88.14,32.77 69.6,32.77 68.83,32 v68.58,31.75 67.56,30.73 v53.34,30.73 53.09,30.99 v46.74,30.99 | v100.33,32 98.3,34.04 v89.92,34.04 | v33.02,35.31 31.5,36.83 23.88,36.83 21.59,39.12 v19.81,39.12 | v17.53,40.64 14.73,40.64 13.97,41.4 U$1.P2 | v39.88,43.94 v46.74,43.94
R1  (via drill 0.61)
  Top 0.254: v29.21,44.45 29.21,46.74 30.23,46.74 E3.5 32,46.99 34.04,46.99 v34.04,50.29 | v14.99,43.43 13.97,44.45 U$1.R1 | E21.14 97.54,42.16 96.27,42.16 96.27,43.69 94.23,45.72 E18.4 92.46,45.97 v91.44,45.97 | v55.88,44.2 56.9,43.18 E9.2 58.67,43.43 59.69,43.43 60.71,44.45 60.71,48.01 v62.23,48.01 63.25,48.01 E12.9 | E6.5 44.7,46.74 v45.72,46.74 45.47,46.99 45.47,50.29 v45.21,50.55 | v83.82,48.01 82.8,48.01 E15.6
  Bottom 0.254: v29.21,44.45 27.18,42.42 18.8,42.42 18.54,42.16 16.26,42.16 v14.99,43.43 | v45.72,46.74 48.26,44.2 v55.88,44.2 | v62.23,48.01 v83.82,48.01 84.07,47.75 89.66,47.75 v91.44,45.97 | v34.04,50.29 34.29,50.55 v45.21,50.55
R2  (via drill 0.61)
  Top 0.254: E3.4 32,45.47 34.54,45.47 35.31,44.7 36.58,44.7 E6.12 36.58,44.2 36.07,44.2 36.07,41.91 | v70.87,35.81 71.12,36.07 71.12,41.66 E12.1 | E8.9 52.32,32 53.34,32 v53.34,33.02 53.09,33.27 53.09,33.53 v51.56,35.05 | v78.99,35.81 78.99,39.62 81.03,41.66 E15.1 | v88.65,34.04 87.88,33.27 E17.8 | v96.52,33.02 97.54,33.02 E20.8 | 36.07,41.91 36.07,39.37 v38.86,36.58 | v16.51,43.18 18.8,40.89 v18.8,40.64 | v35.56,41.91 36.07,41.91
  Bottom 0.254: v53.34,33.02 53.59,32.77 56.13,32.77 57.66,31.24 66.29,31.24 v70.87,35.81 71.12,35.81 v78.99,35.81 79.25,35.56 80.77,34.04 v88.65,34.04 88.9,33.78 89.66,33.02 v96.52,33.02 | v38.86,36.58 43.69,36.58 44.2,36.07 46.99,36.07 48.01,35.05 v51.56,35.05 | v16.51,43.18 15.24,44.45 13.97,44.45 U$1.R2 | v18.8,40.64 19.3,41.15 28.45,41.15 29.21,41.91 v35.56,41.91
S1  (via drill 0.61)
  Top 0.254: E21.12 97.54,44.7 96.01,44.7 96.01,44.96 95.5,45.47 95.5,45.72 94.23,46.99 E18.5 92.46,47.24 v91.44,47.24 | v33.02,48.01 32,48.01 E3.6 | v41.91,48.01 42.93,48.01 E6.6 | 53.85,43.43 52.32,43.43 E9.13 | 53.85,43.43 53.85,47.75 v54.1,48.01 | v62.23,49.28 63.25,49.28 E12.8 | v90.68,42.67 88.9,40.89 88.9,38.86 v86.36,36.32 | v55.37,37.59 53.85,39.12 53.85,43.43 | v14.99,49.02 13.97,49.02 U$1.S1
  Bottom 0.254: v62.23,49.28 61.21,48.26 54.36,48.26 v54.1,48.01 42.16,48.01 v41.91,48.01 v33.02,48.01 32.77,48.26 32,49.02 v14.99,49.02 | v91.44,47.24 92.46,46.23 92.46,42.67 v90.68,42.67 | v86.36,36.32 85.85,36.83 56.13,36.83 v55.37,37.59
S2  (via drill 0.61)
  Top 0.254: v80.01,43.18 81.03,43.18 E15.2 | E12.2 71.37,43.18 v72.39,43.18 72.64,43.43 72.64,49.28 73.66,50.29 v73.66,60.71 73.66,60.96 88.39,60.96 95.76,53.59 95.76,53.34 97.03,53.34 100.08,50.29 100.08,49.02 v100.84,48.26 | v85.09,45.47 86.11,45.47 E18.11 | v102.87,47.24 103.89,47.24 E21.5 | v22.86,43.43 23.88,43.43 E3.13 | v35.56,45.72 36.58,45.72 E6.11 38.35,45.72 39.12,46.48 39.12,57.66 v38.61,58.17 | v48.77,41.15 48.77,35.05 50.55,33.27 E8.8
  Bottom 0.254: v72.39,43.18 v80.01,43.18 80.26,43.43 83.06,43.43 v85.09,45.47 | v102.87,47.24 101.85,48.26 v100.84,48.26 | U$1.S2 13.97,47.75 18.54,47.75 v22.86,43.43 23.11,43.69 24.89,45.47 35.31,45.47 v35.56,45.72 35.81,45.47 39.88,41.4 48.51,41.4 v48.77,41.15 | v73.66,60.71 73.41,60.45 40.89,60.45 v38.61,58.17
T2  (via drill 0.61)
  Top 0.254: v59.69,44.7 58.67,44.7 E9.3 | E12.4 69.6,45.47 69.6,45.21 v68.58,45.21 68.33,44.96 67.06,43.69 v67.06,43.18 | E18.12 86.11,44.2 v85.09,44.2 82.8,44.2 E15.3 81.03,44.45 v80.01,44.45 | v97.79,40.64 99.31,40.64 101.35,42.67 101.35,46.74 99.31,46.74 E21.10 | v18.54,53.85 18.54,54.1 22.1,54.1 22.86,53.34 22.86,52.83 21.84,51.82 21.84,44.7 v22.86,44.7 23.88,44.7 E3.12 | v35.56,46.99 36.58,46.99 E6.10
  Bottom 0.254: v59.69,44.7 60.2,45.21 v68.58,45.21 68.83,45.21 79.25,45.21 v80.01,44.45 | v97.79,40.64 96.77,41.66 87.63,41.66 v85.09,44.2 | v18.54,53.85 17.27,52.58 13.97,52.58 U$1.T2 | v22.86,44.7 24.13,45.97 34.54,45.97 v35.56,46.99 35.81,46.74 36.58,46.74 36.58,45.72 39.37,42.93 39.62,42.93 40.64,41.91 45.97,41.91 46.23,42.16 62.48,42.16 63.5,43.18 v67.06,43.18
U1  (via drill 0.61)
  Top 0.254: v26.67,47.24 25.65,47.24 E3.10 | 14.73,53.34 13.97,54.1 U$1.U1 | 14.73,53.34 v20.07,48.01 | v100.33,43.43 99.31,43.43 E21.13 | v95.25,47.75 94.23,47.75 94.23,48.01 E18.6 | v53.09,52.83 53.09,44.7 52.32,44.7 E9.12 | v107.19,45.97 107.7,46.48 107.7,50.29 v98.55,59.44 | v64.26,59.44 62.48,57.66 R1.2 | 14.73,53.34 v18.54,57.15
  Bottom 0.254: v26.67,47.24 25.91,48.01 v20.07,48.01 | v95.25,47.75 96.01,47.75 v100.33,43.43 100.58,43.69 102.87,45.97 v107.19,45.97 | v53.09,52.83 57.15,56.9 60.45,56.9 R2.1 61.47,56.9 61.72,56.9 R1.2 | v98.55,59.44 97.03,60.96 75.18,60.96 73.66,59.44 v64.26,59.44 64.01,59.18 51.31,59.18 49.28,57.15 v18.54,57.15
U2  (via drill 0.61)
  Top 0.254: v59.69,45.97 58.67,45.97 E9.4 | v68.58,46.48 69.6,46.48 69.6,46.74 E12.5 | v103.12,50.55 103.89,49.78 E21.7 | v93.22,52.32 87.88,46.99 E18.10 86.11,46.74 85.09,46.74 84.33,45.97 82.8,45.97 E15.4 81.03,45.72 v80.01,45.72 | 29.46,50.04 29.46,48.51 25.65,48.51 E3.9 | 29.46,50.04 30.73,51.31 35.56,51.31 | 35.56,51.31 36.07,51.31 36.07,48.77 36.58,48.26 E6.9 | 29.46,50.04 24.38,55.12 17.53,55.12 v17.53,54.86 | v49.02,45.72 48.26,46.48 48.26,49.78 38.86,59.18 35.56,59.18 35.56,51.31
  Bottom 0.254: v103.12,50.55 100.33,53.34 94.23,53.34 v93.22,52.32 | v80.01,45.72 69.34,45.72 68.83,46.23 v68.58,46.48 60.2,46.48 v59.69,45.97 59.44,45.72 v49.02,45.72 | v17.53,54.86 13.97,54.86 U$1.U2
V1  (via drill 0.61)
  Top 0.254: v22.86,50.8 22.86,45.97 23.88,45.97 E3.11 | E9.6 58.67,48.51 60.45,48.51 60.45,54.36 R4.1 | v84.33,53.09 84.33,51.56 86.11,49.78 E18.8 87.88,49.78 v89.92,51.82 | v96.77,50.29 96.77,49.78 97.54,49.78 E21.8 | v14.99,56.13 13.97,57.15 U$1.V1
  Bottom 0.254: 59.44,53.34 60.45,54.36 R4.1 61.47,54.36 61.72,54.36 R3.2 | 59.44,53.34 57.91,51.82 23.88,51.82 v22.86,50.8 22.61,51.05 17.78,55.88 15.24,55.88 v14.99,56.13 | v84.33,53.09 84.07,53.34 59.44,53.34 | v96.77,50.29 96.27,50.8 92.2,50.8 91.19,51.82 v89.92,51.82
V2  (via drill 0.61)
  Top 0.254: E21.9 97.54,48.26 95.25,50.55 95.25,53.34 92.96,53.34 88.65,49.02 88.65,48.51 87.88,48.51 E18.9 86.11,48.26 83.31,51.05 83.31,56.39 79.76,56.39 78.23,54.86 78.23,51.56 76.45,49.78 E15.8 74.68,49.28 73.66,49.28 v73.66,49.02 | v23.88,54.1 23.88,49.78 E3.8 | v36.58,54.1 36.58,49.78 E6.8 | E9.5 56.9,47.24 55.63,47.24 55.63,48.51 54.1,50.04 54.1,53.34 v51.82,55.63 52.07,55.88 62.48,55.88 66.8,51.56 v66.8,49.02 66.8,48.51 69.6,48.51 E12.6
  Bottom 0.254: U$1.V2 13.97,57.15 17.27,57.15 18.29,56.13 21.84,56.13 v23.88,54.1 24.13,54.1 v36.58,54.1 36.83,54.36 38.35,55.88 51.56,55.88 v51.82,55.63 | v66.8,49.02 v73.66,49.02
VCC
  Top 0.381: E21.4 103.89,45.47 103.12,45.47 103.12,40.64 103.89,39.88 C21.1 | E15.14 75.95,41.66 75.95,39.88 C15.1 | E18.14 87.38,41.66 87.38,39.88 C18.1 | E3.14 25.15,41.66 25.15,39.88 C3.1 25.65,38.86 26.42,38.1 26.42,25.91 25.65,25.15 E2.14 25.15,25.15 25.15,23.37 C2.1 | E6.14 37.85,41.66 37.85,39.88 C6.1 | C9.1 51.82,39.88 51.82,41.66 E9.14 50.55,41.91 50.04,42.42 50.04,53.59 50.55,54.1 R4.2 | E12.14 64.52,41.66 64.52,39.88 C12.1 | 104.9,23.37 104.65,23.11 C20.1 | 104.9,23.37 106.17,24.64 106.17,28.96 105.66,28.96 E20.4 | E14.14 75.95,25.15 75.95,23.37 C14.1 | E17.14 87.38,25.15 87.38,23.37 C17.1 | E11.14 64.52,25.15 64.52,23.37 C11.1 | E8.14 51.82,25.15 51.82,23.37 C8.1 | E5.14 37.85,25.15 37.85,23.37 C5.1 | C19.1 104.65,6.6 106.17,8.13 106.17,12.45 105.66,12.45 E19.4 105.66,12.7 106.93,13.97 106.93,21.08 104.9,23.11 104.9,23.37 | E13.14 75.95,8.64 75.95,6.86 C13.1 | E16.14 87.38,8.64 87.38,6.86 C16.1 | E10.14 64.52,8.64 64.52,6.86 C10.1 | E7.14 51.82,8.64 51.82,6.86 C7.1 | E4.14 37.85,8.64 37.85,6.86 C4.1 | E1.14 25.15,8.64 25.15,6.86 C1.1
  Bottom 0.381: 86.36,38.35 87.12,39.12 C18.1 | 86.36,38.35 86.11,38.1 77.72,38.1 76.71,39.12 C15.1 75.69,39.37 71.63,39.37 70.36,38.1 63.5,38.1 63.5,38.35 | C21.1 103.63,39.12 102.62,38.1 86.36,38.1 86.36,38.35 | C3.1 25.91,39.12 26.92,38.1 32.26,38.1 33.27,39.12 37.59,39.12 C6.1 38.61,39.12 39.62,38.1 43.69,38.1 44.7,39.12 51.56,39.12 C9.1 52.58,39.12 53.09,38.61 56.13,38.61 56.64,38.1 63.25,38.1 63.5,38.35 | R4.2 51.31,54.61 52.32,54.61 52.83,55.12 52.83,56.64 51.05,56.64 R2.2 | 63.5,38.35 64.26,39.12 C12.1 | C20.1 103.63,22.61 101.85,20.83 89.92,20.83 88.14,22.61 C17.1 87.12,22.61 86.11,21.59 77.72,21.59 76.71,22.61 C14.1 75.69,22.61 74.68,21.59 69.34,21.59 68.33,22.61 65.28,22.61 C11.1 64.26,22.61 64.01,22.35 58.42,22.35 57.66,21.59 50.8,21.59 50.8,21.84 | 36.83,21.84 37.59,22.61 C5.1 | 36.83,21.84 36.58,21.59 26.92,21.59 25.91,22.61 C2.1 | 50.8,21.84 50.55,21.59 36.83,21.59 36.83,21.84 | 50.8,21.84 51.56,22.61 C8.1 | 86.36,5.33 87.12,6.1 C16.1 | 86.36,5.33 86.11,5.08 77.72,5.08 76.71,6.1 C13.1 75.69,6.35 71.63,6.35 70.36,5.08 63.5,5.08 63.5,5.33 | C19.1 103.63,6.1 102.62,5.08 86.36,5.08 86.36,5.33 | U$1.A2 13.97,5.08 15.24,6.35 24.89,6.35 C1.1 25.91,6.1 26.92,5.08 36.58,5.08 36.83,5.33 | 36.83,5.33 37.59,6.1 C4.1 | 50.8,5.33 50.55,5.08 36.83,5.08 36.83,5.33 | 50.8,5.33 51.56,6.1 C7.1 | 63.5,5.33 63.25,5.08 50.8,5.08 50.8,5.33 | 63.5,5.33 64.26,6.1 C10.1

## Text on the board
Bottom: VRS | M111/M113/M115/M117/M119/M206/M209
tNames: M113/M117/M119: | M111 | M113 | M115 | M117 | M119 | Fill Only One Row. | M111/M115/M206/M207: Remove Resistors. | M111/M113/M115/M117/M119/M206/M207
tValues: A1 | Add Resistors. | K2 | A1 | K2 | M207 | M206/M216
